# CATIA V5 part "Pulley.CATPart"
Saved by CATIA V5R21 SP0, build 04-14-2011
Part number: Pulley
Bounding box of the stored display mesh (mm): x -40.838 to 40.838, y -33 to 33, z -40.838 to 40.838
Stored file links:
  D:\CATIA V5R21 E-RESOURCES\CATIA-V5R21\catia-v5r21-Prts\c12_catia_v5r21_prt\c12_catia_v5r21figr_12-53\Pulley.CATPart
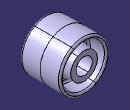
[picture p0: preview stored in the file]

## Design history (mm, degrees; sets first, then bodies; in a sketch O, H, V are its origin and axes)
Body1 (main body)
  Sketch1 on yz-plane, origin (0, 0, 0), H (0, 1, 0), V (0, 0, 1)
    line L1 (0, 13.45) -> (31.5, 13.45)
    point P1 (0, 13.45)
    point P2 (31.5, 13.45)
    line L2 (31.5, 13.45) -> (31.5, 22)
    point P3 (31.5, 22)
    line L3 (31.5, 22) -> (6, 24)
    point P4 (6, 24)
    line L4 (6, 24) -> (6, 33)
    point P5 (6, 33)
    line L5 (6, 33) -> (33, 35)
    point P6 (33, 35)
    line L6 (33, 35) -> (33, 41)
    point P7 (33, 41)
    line L7 (33, 41) -> (0, 41)
    point P8 (0, 41)
    point P9 (0, 41)
    point P10 (-33, 41)
    line L8 (-33, 41) -> (0, 41)
    point P11 (-33, 35)
    line L9 (-33, 35) -> (-33, 41)
    point P12 (-6, 33)
    line L10 (-6, 33) -> (-33, 35)
    point P13 (-6, 24)
    line L11 (-6, 24) -> (-6, 33)
    point P14 (-31.5, 22)
    line L12 (-31.5, 22) -> (-6, 24)
    point P15 (-31.5, 13.45)
    line L13 (-31.5, 13.45) -> (-31.5, 22)
    point P16 (0, 13.45)
    line L14 (0, 13.45) -> (-31.5, 13.45)
    length L1 = 31.5
    distance L1 H = 13.45
    distance P4 H = 24
    distance P3 H = 22
    distance L4 V = 6
    distance P5 H = 33
    distance P6 H = 35
    distance V L6 = 33
    distance L7 H = 41
    coincidence: P1 V, P8 V, P1 P16, P8 P9
    horizontal: L1 H, L7 H
    vertical: L2 V, L4 V, L6 V
    symmetry: P8 P9 V, P7 P10 V, L7 L8 V, P6 P11 V, L6 L9 V, P5 P12 V, L5 L10 V, P4 P13 V, L4 L11 V, P3 P14 V, L3 L12 V, P2 P15 V, L2 L13 V, P1 P16 V, L1 L14 V
  Shaft1: profile Sketch1, axis Sketch1.H, angle 360
  Fillet1: radius 3, on 4 faces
